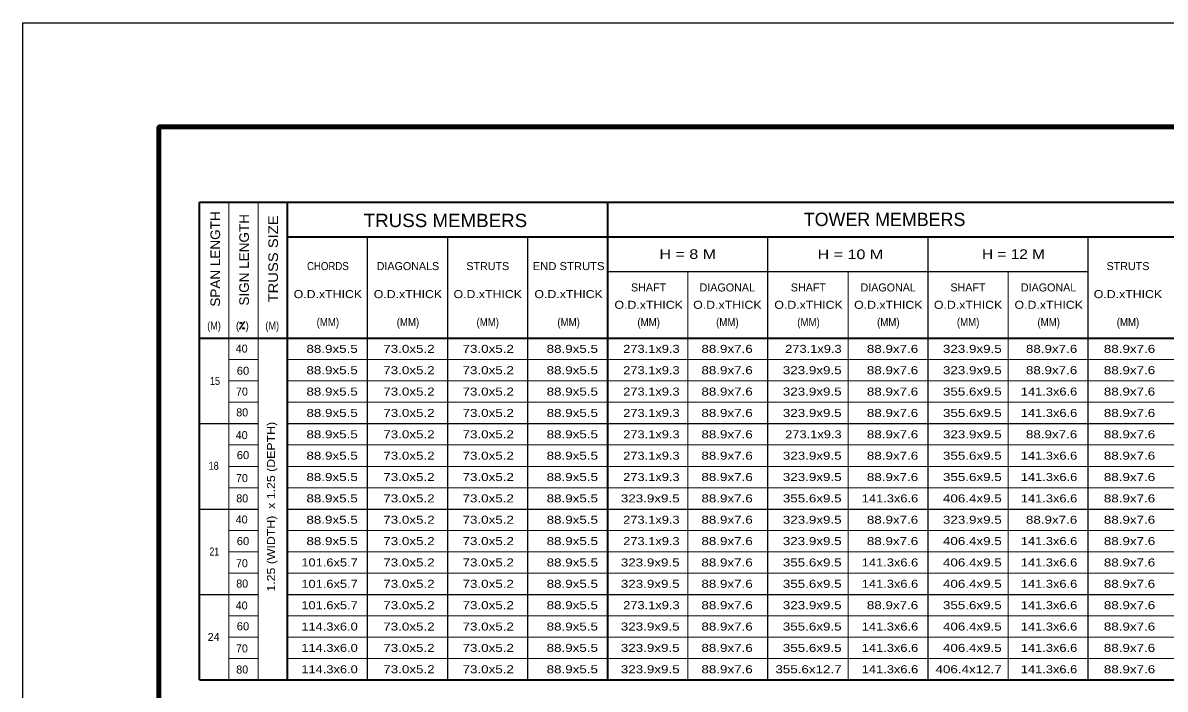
# Model space of a CAD drawing. Extents: x 312601.858 to 312602.699, y 144420.11 to 144420.704.
# Drawn here: x 312601.8579 to 312602.2859, y 144420.4541 to 144420.7036 of the extents above; entities that cross this region are included whole.
import ezdxf
from ezdxf.enums import TextEntityAlignment as Align

# ---------------------------------------------------------------- set-up
doc = ezdxf.new("R2010")
doc.units = 0
doc.header["$LTSCALE"] = 0.0012
for name, color, linetype, lineweight in [('1', 7, 'Continuous', 25), ('2', 7, 'Continuous', 13), ('39', 7, 'Continuous', 13)]:
    doc.layers.add(name, color=color, linetype=linetype, lineweight=lineweight)

msp = doc.modelspace()

# ---------------------------------------------------------------- linework, layer by layer
at = {"layer": '1', "lineweight": 35}
for p, q in [((312601.9241, 144420.4575), (312601.9241, 144420.6365)), ((312601.9241, 144420.6365), (312602.6651, 144420.6365)), ((312601.9571, 144420.4575), (312601.9571, 144420.6365)), ((312602.0771, 144420.4575), (312602.0771, 144420.6365)), ((312601.9571, 144420.6235), (312602.6321, 144420.6235)), ((312601.9241, 144420.5855), (312602.6651, 144420.5855)), ((312601.9241, 144420.4575), (312602.665, 144420.4575))]:
    msp.add_line(p, q, dxfattribs=at)
at = {"layer": '1', "lineweight": 13}
for p, q in [((312601.9351, 144420.4575), (312601.9351, 144420.6365)), ((312601.9461, 144420.4575), (312601.9461, 144420.6365)), ((312602.1071, 144420.4575), (312602.1071, 144420.6105)), ((312602.1671, 144420.4575), (312602.1671, 144420.6105)), ((312602.2271, 144420.4575), (312602.2271, 144420.6105)), ((312602.0321, 144420.5855), (312602.2121, 144420.5855)), ((312602.0321, 144420.5855), (312602.2121, 144420.5855)), ((312601.9351, 144420.5775), (312601.9461, 144420.5775)), ((312601.9571, 144420.5775), (312602.6321, 144420.5775)), ((312601.9351, 144420.5695), (312601.9461, 144420.5695)), ((312601.9573, 144420.5695), (312602.6321, 144420.5695)), ((312601.9351, 144420.5615), (312601.9461, 144420.5615)), ((312601.9573, 144420.5615), (312602.6321, 144420.5615)), ((312601.9351, 144420.5455), (312601.9461, 144420.5455)), ((312601.9351, 144420.5455), (312601.9454, 144420.5455)), ((312601.9573, 144420.5455), (312602.6321, 144420.5455)), ((312601.9351, 144420.5375), (312601.9461, 144420.5375)), ((312601.9573, 144420.5375), (312602.6321, 144420.5375)), ((312601.9351, 144420.5295), (312601.9461, 144420.5295)), ((312601.9573, 144420.5295), (312602.6321, 144420.5295)), ((312601.9351, 144420.5135), (312601.9461, 144420.5135)), ((312601.9573, 144420.5135), (312602.6321, 144420.5135)), ((312601.9351, 144420.5055), (312601.9461, 144420.5055)), ((312601.9573, 144420.5055), (312602.6321, 144420.5055)), ((312601.9351, 144420.4975), (312601.9461, 144420.4975)), ((312601.9573, 144420.4975), (312602.6321, 144420.4975)), ((312601.9351, 144420.4815), (312601.9461, 144420.4815)), ((312601.9573, 144420.4815), (312602.6321, 144420.4815)), ((312601.9351, 144420.4735), (312601.9461, 144420.4735)), ((312601.9573, 144420.4735), (312602.6321, 144420.4735)), ((312601.9351, 144420.4655), (312601.9461, 144420.4655)), ((312601.9573, 144420.4655), (312602.6321, 144420.4655))]:
    msp.add_line(p, q, dxfattribs=at)
at = {"layer": '1'}
for p, q in [((312601.9871, 144420.4575), (312601.9871, 144420.6235)), ((312602.0171, 144420.4575), (312602.0171, 144420.6235)), ((312602.0471, 144420.4575), (312602.0471, 144420.6235)), ((312602.1371, 144420.4575), (312602.1371, 144420.6235)), ((312602.1971, 144420.4575), (312602.1971, 144420.6235)), ((312602.2571, 144420.4575), (312602.2571, 144420.6235)), ((312602.0771, 144420.6105), (312602.2571, 144420.6105)), ((312601.9391, 144420.5887), (312601.9411, 144420.5917)), ((312601.9241, 144420.5535), (312601.9461, 144420.5535)), ((312601.9573, 144420.5535), (312602.6321, 144420.5535)), ((312601.9241, 144420.5215), (312601.9461, 144420.5215)), ((312601.9573, 144420.5215), (312602.6321, 144420.5215)), ((312601.9241, 144420.4895), (312601.9461, 144420.4895)), ((312601.9573, 144420.4895), (312602.6321, 144420.4895))]:
    msp.add_line(p, q, dxfattribs=at)
for centre in [(312601.9396, 144420.5912), (312601.9406, 144420.5892)]:
    msp.add_circle(centre, 0.0003, dxfattribs=at)
at = {"layer": '39', "lineweight": 25}
for p, q in [((312601.8579, 144420.7036), (312602.6989, 144420.7036)), ((312601.8579, 144420.1096), (312601.8579, 144420.7036))]:
    msp.add_line(p, q, dxfattribs=at)
at = {"layer": '39', "lineweight": 158}
msp.add_lwpolyline([(312601.9089, 144420.1248), (312601.9089, 144420.6646), (312602.6839, 144420.6646)], dxfattribs=at)

# ---------------------------------------------------------------- texts
at = {"layer": '1'}
for s, height, width, p in [('SPAN LENGTH', 0.0036, 1.05, (312601.9318, 144420.61515)), ('SIGN LENGTH', 0.0036, 1.05, (312601.9426, 144420.61485)), ('TRUSS SIZE', 0.0036, 1.15, (312601.9535, 144420.6152)), ('1.25 (WIDTH)  x 1.25 (DEPTH) ', 0.003, 1.15, (312601.9524, 144420.523))]:
    msp.add_text(s, height=height, rotation=90, dxfattribs=dict(at, width=width)).set_placement(p, align=Align.CENTER)
for s, height, width, p in [('TRUSS MEMBERS', 0.005, 1.05, (312602.01625, 144420.6271)), ('H = 8 M', 0.0036, 1.25, (312602.10705, 144420.6152)), ('H = 10 M', 0.0036, 1.25, (312602.168, 144420.6151)), ('H = 12 M', 0.0036, 1.2, (312602.2291, 144420.6152)), ('CHORDS', 0.003, 0.9, (312601.9722, 144420.611)), ('END STRUTS', 0.003, 1.05, (312602.0624, 144420.611)), ('O.D.xTHICK', 0.003, 1.15, (312601.9722, 144420.6005)), ('O.D.xTHICK', 0.003, 1.15, (312602.0022, 144420.6005)), ('O.D.xTHICK', 0.003, 1.15, (312602.0321, 144420.6005)), ('O.D.xTHICK', 0.003, 1.15, (312602.0624, 144420.6005)), ('O.D.xTHICK', 0.003, 1.15, (312602.272, 144420.6005)), ('O.D.xTHICK', 0.003, 1.15, (312602.0924, 144420.5965)), ('O.D.xTHICK', 0.003, 1.15, (312602.1219, 144420.5965)), ('O.D.xTHICK', 0.003, 1.15, (312602.1523, 144420.5965)), ('O.D.xTHICK', 0.003, 1.15, (312602.1822, 144420.5965)), ('O.D.xTHICK', 0.003, 1.15, (312602.2121, 144420.5965)), ('O.D.xTHICK', 0.003, 1.15, (312602.2423, 144420.5965)), ('(MM)', 0.003, 0.9, (312601.9722, 144420.59)), ('(MM)', 0.003, 0.9, (312602.0022, 144420.59)), ('(MM)', 0.003, 0.9, (312602.0321, 144420.59)), ('(MM)', 0.003, 0.9, (312602.0624, 144420.59)), ('(MM)', 0.003, 0.9, (312602.0924, 144420.59)), ('(MM)', 0.003, 0.9, (312602.1219, 144420.59)), ('(MM)', 0.003, 0.9, (312602.1523, 144420.59)), ('(MM)', 0.003, 0.9, (312602.1822, 144420.59)), ('(MM)', 0.003, 0.9, (312602.2121, 144420.59)), ('(MM)', 0.003, 0.9, (312602.2423, 144420.59)), ('(MM)', 0.003, 0.9, (312602.272, 144420.59)), ('(M)', 0.003, 0.85, (312601.92955, 144420.5887)), ('(M)', 0.003, 0.85, (312601.95135, 144420.5887)), ('60', 0.003, 1.05, (312601.9404, 144420.5718)), ('15', 0.003, 0.85, (312601.9299, 144420.568)), ('60', 0.003, 1.05, (312601.9404, 144420.5402)), ('18', 0.003, 0.85, (312601.9294, 144420.5362)), ('21', 0.003, 0.8, (312601.92965, 144420.5041)), ('60', 0.003, 1.05, (312601.9404, 144420.508)), ('60', 0.003, 1.05, (312601.9404, 144420.4761))]:
    msp.add_text(s, height=height, dxfattribs=dict(at, width=width)).set_placement(p, align=Align.CENTER)
for s, height, p in [('TOWER MEMBERS', 0.005, (312602.1808, 144420.6275)), ('DIAGONALS', 0.003, (312602.0022, 144420.611)), ('STRUTS', 0.003, (312602.0321, 144420.611)), ('STRUTS', 0.003, (312602.272, 144420.611)), ('SHAFT', 0.003, (312602.09235, 144420.603)), ('DIAGONAL', 0.003, (312602.12185, 144420.603)), ('SHAFT', 0.003, (312602.15225, 144420.603)), ('DIAGONAL', 0.003, (312602.18215, 144420.603)), ('SHAFT', 0.003, (312602.21205, 144420.603)), ('DIAGONAL', 0.003, (312602.24225, 144420.603)), ('(  )', 0.003, (312601.94015, 144420.5887)), ('40', 0.003, (312601.9399, 144420.5801)), ('70', 0.003, (312601.94, 144420.564)), ('80', 0.003, (312601.9401, 144420.5562)), ('40', 0.003, (312601.9399, 144420.5477)), ('70', 0.003, (312601.94, 144420.5316)), ('80', 0.003, (312601.9401, 144420.524)), ('40', 0.003, (312601.9399, 144420.5161)), ('70', 0.003, (312601.94, 144420.4997)), ('80', 0.003, (312601.9401, 144420.4921)), ('40', 0.003, (312601.9399, 144420.4839)), ('24', 0.003, (312601.9294, 144420.4721)), ('70', 0.003, (312601.94, 144420.4678)), ('80', 0.003, (312601.9401, 144420.4599))]:
    msp.add_text(s, height=height, dxfattribs=at).set_placement(p, align=Align.CENTER)
at = {"layer": '2'}
for s, width, p in [('88.9x5.5', 1.25, (312601.9834, 144420.58)), ('73.0x5.2', 1.25, (312602.0122, 144420.58)), ('73.0x5.2', 1.25, (312602.0419, 144420.58)), ('88.9x5.5', 1.25, (312602.0734, 144420.58)), ('273.1x9.3', 1.2, (312602.104, 144420.58)), ('88.9x7.6', 1.25, (312602.1314, 144420.58)), ('273.1x9.3', 1.2, (312602.1647, 144420.58)), ('88.9x7.6', 1.25, (312602.1934, 144420.58)), ('323.9x9.5', 1.25, (312602.2247, 144420.58)), ('88.9x7.6', 1.25, (312602.253, 144420.58)), ('88.9x7.6', 1.25, (312602.2822, 144420.58)), ('88.9x5.5', 1.25, (312601.9834, 144420.572)), ('73.0x5.2', 1.25, (312602.0122, 144420.572)), ('73.0x5.2', 1.25, (312602.0419, 144420.572)), ('88.9x5.5', 1.25, (312602.0734, 144420.572)), ('273.1x9.3', 1.2, (312602.104, 144420.572)), ('88.9x7.6', 1.25, (312602.1314, 144420.572)), ('323.9x9.5', 1.25, (312602.1647, 144420.572)), ('88.9x7.6', 1.25, (312602.1934, 144420.572)), ('323.9x9.5', 1.25, (312602.2247, 144420.572)), ('88.9x7.6', 1.25, (312602.253, 144420.572)), ('88.9x7.6', 1.25, (312602.2822, 144420.572)), ('88.9x5.5', 1.25, (312601.9834, 144420.564)), ('73.0x5.2', 1.25, (312602.0122, 144420.564)), ('73.0x5.2', 1.25, (312602.0419, 144420.564)), ('88.9x5.5', 1.25, (312602.0734, 144420.564)), ('273.1x9.3', 1.2, (312602.104, 144420.564)), ('88.9x7.6', 1.25, (312602.1314, 144420.564)), ('323.9x9.5', 1.25, (312602.1647, 144420.564)), ('88.9x7.6', 1.25, (312602.1934, 144420.564)), ('355.6x9.5', 1.25, (312602.2247, 144420.564)), ('141.3x6.6', 1.2, (312602.253, 144420.564)), ('88.9x7.6', 1.25, (312602.2822, 144420.564)), ('88.9x5.5', 1.25, (312601.9834, 144420.556)), ('73.0x5.2', 1.25, (312602.0122, 144420.556)), ('73.0x5.2', 1.25, (312602.0419, 144420.556)), ('88.9x5.5', 1.25, (312602.0734, 144420.556)), ('273.1x9.3', 1.2, (312602.104, 144420.556)), ('88.9x7.6', 1.25, (312602.1314, 144420.556)), ('323.9x9.5', 1.25, (312602.1647, 144420.556)), ('88.9x7.6', 1.25, (312602.1934, 144420.556)), ('355.6x9.5', 1.25, (312602.2247, 144420.556)), ('141.3x6.6', 1.2, (312602.253, 144420.556)), ('88.9x7.6', 1.25, (312602.2822, 144420.556)), ('88.9x5.5', 1.25, (312601.9834, 144420.548)), ('73.0x5.2', 1.25, (312602.0122, 144420.548)), ('73.0x5.2', 1.25, (312602.0419, 144420.548)), ('88.9x5.5', 1.25, (312602.0734, 144420.548)), ('273.1x9.3', 1.2, (312602.104, 144420.548)), ('88.9x7.6', 1.25, (312602.1314, 144420.548)), ('273.1x9.3', 1.2, (312602.1647, 144420.548)), ('88.9x7.6', 1.25, (312602.1934, 144420.548)), ('323.9x9.5', 1.25, (312602.2247, 144420.548)), ('88.9x7.6', 1.25, (312602.253, 144420.548)), ('88.9x7.6', 1.25, (312602.2822, 144420.548)), ('88.9x5.5', 1.25, (312601.9834, 144420.54)), ('73.0x5.2', 1.25, (312602.0122, 144420.54)), ('73.0x5.2', 1.25, (312602.0419, 144420.54)), ('88.9x5.5', 1.25, (312602.0734, 144420.54)), ('273.1x9.3', 1.2, (312602.104, 144420.54)), ('88.9x7.6', 1.25, (312602.1314, 144420.54)), ('323.9x9.5', 1.25, (312602.1647, 144420.54)), ('88.9x7.6', 1.25, (312602.1934, 144420.54)), ('355.6x9.5', 1.25, (312602.2247, 144420.54)), ('141.3x6.6', 1.2, (312602.253, 144420.54)), ('88.9x7.6', 1.25, (312602.2822, 144420.54)), ('88.9x5.5', 1.25, (312601.9834, 144420.532)), ('73.0x5.2', 1.25, (312602.0122, 144420.532)), ('73.0x5.2', 1.25, (312602.0419, 144420.532)), ('88.9x5.5', 1.25, (312602.0734, 144420.532)), ('273.1x9.3', 1.2, (312602.104, 144420.532)), ('88.9x7.6', 1.25, (312602.1314, 144420.532)), ('323.9x9.5', 1.25, (312602.1647, 144420.532)), ('88.9x7.6', 1.25, (312602.1934, 144420.532)), ('355.6x9.5', 1.25, (312602.2247, 144420.532)), ('141.3x6.6', 1.2, (312602.253, 144420.532)), ('88.9x7.6', 1.25, (312602.2822, 144420.532)), ('88.9x5.5', 1.25, (312601.9834, 144420.524)), ('73.0x5.2', 1.25, (312602.0122, 144420.524)), ('73.0x5.2', 1.25, (312602.0419, 144420.524)), ('88.9x5.5', 1.25, (312602.0734, 144420.524)), ('323.9x9.5', 1.25, (312602.104, 144420.524)), ('88.9x7.6', 1.25, (312602.1314, 144420.524)), ('355.6x9.5', 1.25, (312602.1647, 144420.524)), ('141.3x6.6', 1.2, (312602.1934, 144420.524)), ('406.4x9.5', 1.25, (312602.2247, 144420.524)), ('141.3x6.6', 1.2, (312602.253, 144420.524)), ('88.9x7.6', 1.25, (312602.2822, 144420.524)), ('88.9x5.5', 1.25, (312601.9834, 144420.516)), ('73.0x5.2', 1.25, (312602.0122, 144420.516)), ('73.0x5.2', 1.25, (312602.0419, 144420.516)), ('88.9x5.5', 1.25, (312602.0734, 144420.516)), ('273.1x9.3', 1.2, (312602.104, 144420.516)), ('88.9x7.6', 1.25, (312602.1314, 144420.516)), ('323.9x9.5', 1.25, (312602.1647, 144420.516)), ('88.9x7.6', 1.25, (312602.1934, 144420.516)), ('323.9x9.5', 1.25, (312602.2247, 144420.516)), ('88.9x7.6', 1.25, (312602.253, 144420.516)), ('88.9x7.6', 1.25, (312602.2822, 144420.516)), ('88.9x5.5', 1.25, (312601.9834, 144420.508)), ('73.0x5.2', 1.25, (312602.0122, 144420.508)), ('73.0x5.2', 1.25, (312602.0419, 144420.508)), ('88.9x5.5', 1.25, (312602.0734, 144420.508)), ('273.1x9.3', 1.2, (312602.104, 144420.508)), ('88.9x7.6', 1.25, (312602.1314, 144420.508)), ('323.9x9.5', 1.25, (312602.1647, 144420.508)), ('88.9x7.6', 1.25, (312602.1934, 144420.508)), ('406.4x9.5', 1.25, (312602.2247, 144420.508)), ('141.3x6.6', 1.2, (312602.253, 144420.508)), ('88.9x7.6', 1.25, (312602.2822, 144420.508)), ('101.6x5.7', 1.2, (312601.9834, 144420.5)), ('73.0x5.2', 1.25, (312602.0122, 144420.5)), ('73.0x5.2', 1.25, (312602.0419, 144420.5)), ('88.9x5.5', 1.25, (312602.0734, 144420.5)), ('323.9x9.5', 1.25, (312602.104, 144420.5)), ('88.9x7.6', 1.25, (312602.1314, 144420.5)), ('355.6x9.5', 1.25, (312602.1647, 144420.5)), ('141.3x6.6', 1.2, (312602.1934, 144420.5)), ('406.4x9.5', 1.25, (312602.2247, 144420.5)), ('141.3x6.6', 1.2, (312602.253, 144420.5)), ('88.9x7.6', 1.25, (312602.2822, 144420.5)), ('101.6x5.7', 1.2, (312601.9834, 144420.492)), ('73.0x5.2', 1.25, (312602.0122, 144420.492)), ('73.0x5.2', 1.25, (312602.0419, 144420.492)), ('88.9x5.5', 1.25, (312602.0734, 144420.492)), ('323.9x9.5', 1.25, (312602.104, 144420.492)), ('88.9x7.6', 1.25, (312602.1314, 144420.492)), ('355.6x9.5', 1.25, (312602.1647, 144420.492)), ('141.3x6.6', 1.2, (312602.1934, 144420.492)), ('406.4x9.5', 1.25, (312602.2247, 144420.492)), ('141.3x6.6', 1.2, (312602.253, 144420.492)), ('88.9x7.6', 1.25, (312602.2822, 144420.492)), ('101.6x5.7', 1.2, (312601.9834, 144420.484)), ('73.0x5.2', 1.25, (312602.0122, 144420.484)), ('73.0x5.2', 1.25, (312602.0419, 144420.484)), ('88.9x5.5', 1.25, (312602.0734, 144420.484)), ('273.1x9.3', 1.2, (312602.104, 144420.484)), ('88.9x7.6', 1.25, (312602.1314, 144420.484)), ('323.9x9.5', 1.25, (312602.1647, 144420.484)), ('88.9x7.6', 1.25, (312602.1934, 144420.484)), ('355.6x9.5', 1.25, (312602.2247, 144420.484)), ('141.3x6.6', 1.2, (312602.253, 144420.484)), ('88.9x7.6', 1.25, (312602.2822, 144420.484)), ('114.3x6.0', 1.2, (312601.9834, 144420.476)), ('73.0x5.2', 1.25, (312602.0122, 144420.476)), ('73.0x5.2', 1.25, (312602.0419, 144420.476)), ('88.9x5.5', 1.25, (312602.0734, 144420.476)), ('323.9x9.5', 1.25, (312602.104, 144420.476)), ('88.9x7.6', 1.25, (312602.1314, 144420.476)), ('355.6x9.5', 1.25, (312602.1647, 144420.476)), ('141.3x6.6', 1.2, (312602.1934, 144420.476)), ('406.4x9.5', 1.25, (312602.2247, 144420.476)), ('141.3x6.6', 1.2, (312602.253, 144420.476)), ('88.9x7.6', 1.25, (312602.2822, 144420.476)), ('114.3x6.0', 1.2, (312601.9834, 144420.468)), ('73.0x5.2', 1.25, (312602.0122, 144420.468)), ('73.0x5.2', 1.25, (312602.0419, 144420.468)), ('88.9x5.5', 1.25, (312602.0734, 144420.468)), ('323.9x9.5', 1.25, (312602.104, 144420.468)), ('88.9x7.6', 1.25, (312602.1314, 144420.468)), ('355.6x9.5', 1.25, (312602.1647, 144420.468)), ('141.3x6.6', 1.2, (312602.1934, 144420.468)), ('406.4x9.5', 1.25, (312602.2247, 144420.468)), ('141.3x6.6', 1.2, (312602.253, 144420.468)), ('88.9x7.6', 1.25, (312602.2822, 144420.468)), ('114.3x6.0', 1.2, (312601.9834, 144420.46)), ('73.0x5.2', 1.25, (312602.0122, 144420.46)), ('73.0x5.2', 1.25, (312602.0419, 144420.46)), ('88.9x5.5', 1.25, (312602.0734, 144420.46)), ('323.9x9.5', 1.25, (312602.104, 144420.46)), ('88.9x7.6', 1.25, (312602.1314, 144420.46)), ('355.6x12.7', 1.25, (312602.1647, 144420.46)), ('141.3x6.6', 1.2, (312602.1934, 144420.46)), ('406.4x12.7', 1.25, (312602.2247, 144420.46)), ('141.3x6.6', 1.2, (312602.253, 144420.46)), ('88.9x7.6', 1.25, (312602.2822, 144420.46))]:
    msp.add_text(s, height=0.003, dxfattribs=dict(at, width=width)).set_placement(p, align=Align.RIGHT)

doc.saveas('drawing.dxf')
